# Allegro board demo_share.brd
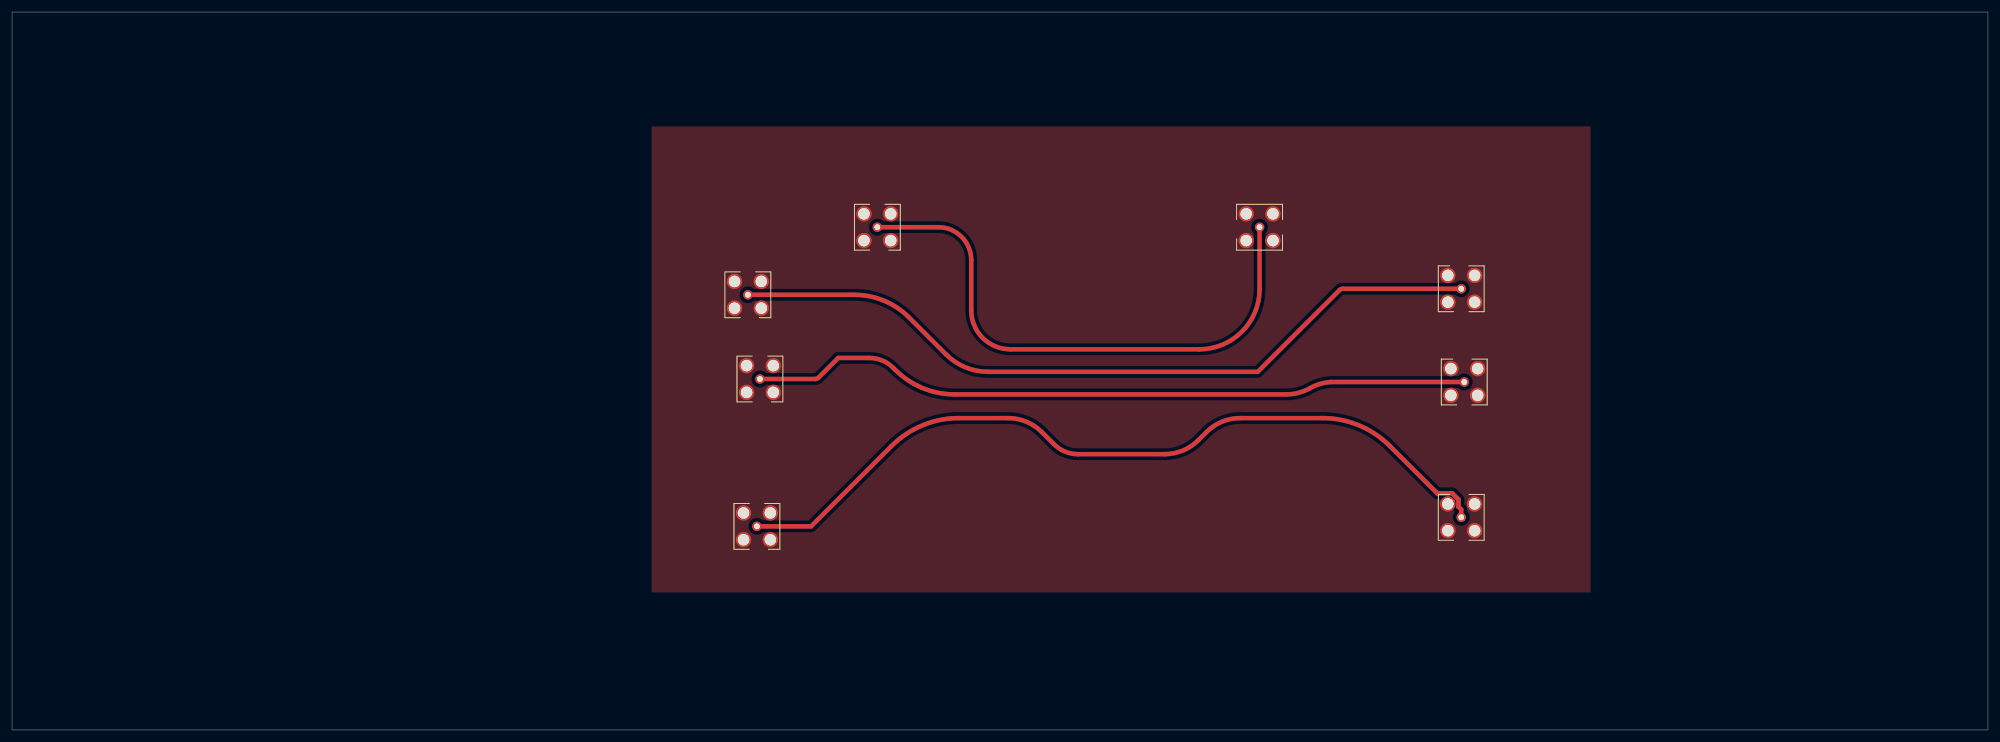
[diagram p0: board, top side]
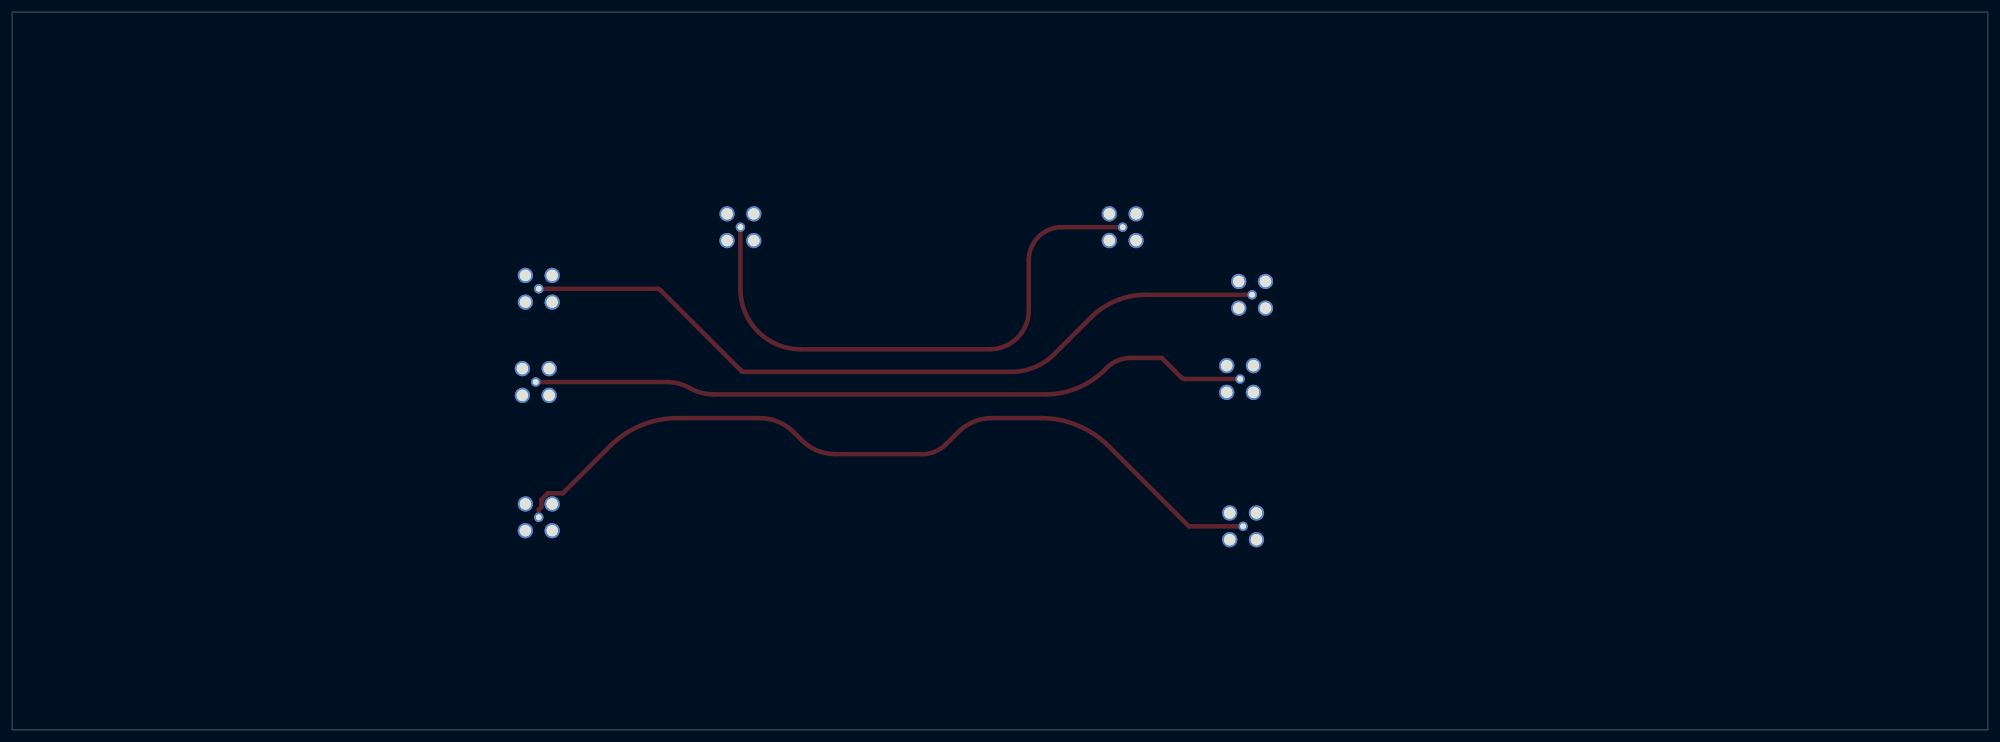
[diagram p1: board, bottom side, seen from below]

Outline 328.24 x 119.38 mm; copper layers: TOP, L2, L3, L4, L5, BOTTOM. Coordinates in mm from the lower left corner of the outline.
Outline path: 0,119.38 0,0 328.24,0 328.24,119.38 0,119.38

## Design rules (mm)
constraint set DEFAULT: min track width 0.127

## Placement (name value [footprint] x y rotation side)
J1  -  [BNC]  143.74 83.6 180 top
J2  -  [BNC]  207.24 83.6 90 top
J3  -  [BNC]  123.74 33.86 180 top
J4  -  [BNC]  240.74 35.36 0 top
J6  -  [BNC]  122.24 72.36 180 top
J7  -  [BNC]  240.74 73.36 0 top
J8  -  [BNC]  124.24 58.36 180 top
J9  -  [BNC]  241.24 57.86 0 top

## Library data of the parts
J1-J4 J6-J9 = DUMMY_BNC

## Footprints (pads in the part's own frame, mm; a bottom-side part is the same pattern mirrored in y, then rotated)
BNC
  round 1.575 hole 0.965: 1(0,0)
  round 2.54 hole 1.905: 2(-2.223,2.223) 3(-2.223,-2.223) 4(2.223,2.223) 5(2.223,-2.223)

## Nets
GND: J1.2 J1.3 J1.4 J1.5 J2.2 J2.3 J2.4 J2.5 J3.2 J3.3 J3.4 J3.5 J4.2 J4.3 J4.4 J4.5 J6.2 J6.3 J6.4 J6.5 J7.2 J7.3 J7.4 J7.5 J8.2 J8.3 J8.4 J8.5 J9.2 J9.3 J9.4 J9.5
SIG1: J1.1 J2.1
SIG2: J6.1 J7.1
SIG3: J8.1 J9.1
SIG4: J3.1 J4.1

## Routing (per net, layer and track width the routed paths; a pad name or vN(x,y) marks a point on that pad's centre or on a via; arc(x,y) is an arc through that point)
SIG1: length 94.7
  TOP w0.75: J2.1 207.24,73.3 arc(204.31,66.23) 197.24,63.3 165.82,63.3 arc(161.24,65.2) 159.34,69.78 159.34,78.14 arc(157.74,82) 153.88,83.6 J1.1
SIG2: length 128.5
  TOP w0.75: J7.1 221.05,73.36 arc(220.76,73.3) 220.52,73.14 206.93,59.55 162.17,59.55 arc(158.36,60.31) 155.13,62.47 149,68.6 arc(144.84,71.38) 139.93,72.36 J6.1
SIG3: length 120.4
  TOP w0.75: J9.1 219.15,57.86 arc(217.33,57.55) 215.62,56.84 arc(213.71,56.06) 211.67,55.8 156.57,55.8 arc(151.24,56.86) 146.72,59.88 146.38,60.22 arc(144.56,61.43) 142.42,61.86 137.24,61.86 133.96,58.58 arc(133.72,58.42) 133.43,58.36 J8.1
SIG4: length 135.1
  TOP w0.75: J4.1 240.74,36.65 240.29,37.1 240.29,38.32 239.25,39.35 236.75,39.35 228.88,47.22 arc(223.74,50.65) 217.67,51.86 204.02,51.86 arc(200.99,51.26) 198.42,49.54 197.06,48.18 arc(194.49,46.46) 191.46,45.86 177.06,45.86 arc(174.92,46.29) 173.1,47.5 171.06,49.54 arc(168.49,51.26) 165.46,51.86 157.31,51.86 arc(151.24,50.65) 146.1,47.22 132.74,33.86 J3.1

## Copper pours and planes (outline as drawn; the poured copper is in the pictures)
GND on TOP: 106.24,100.36 106.24,22.86 262.24,22.86 262.24,100.36
